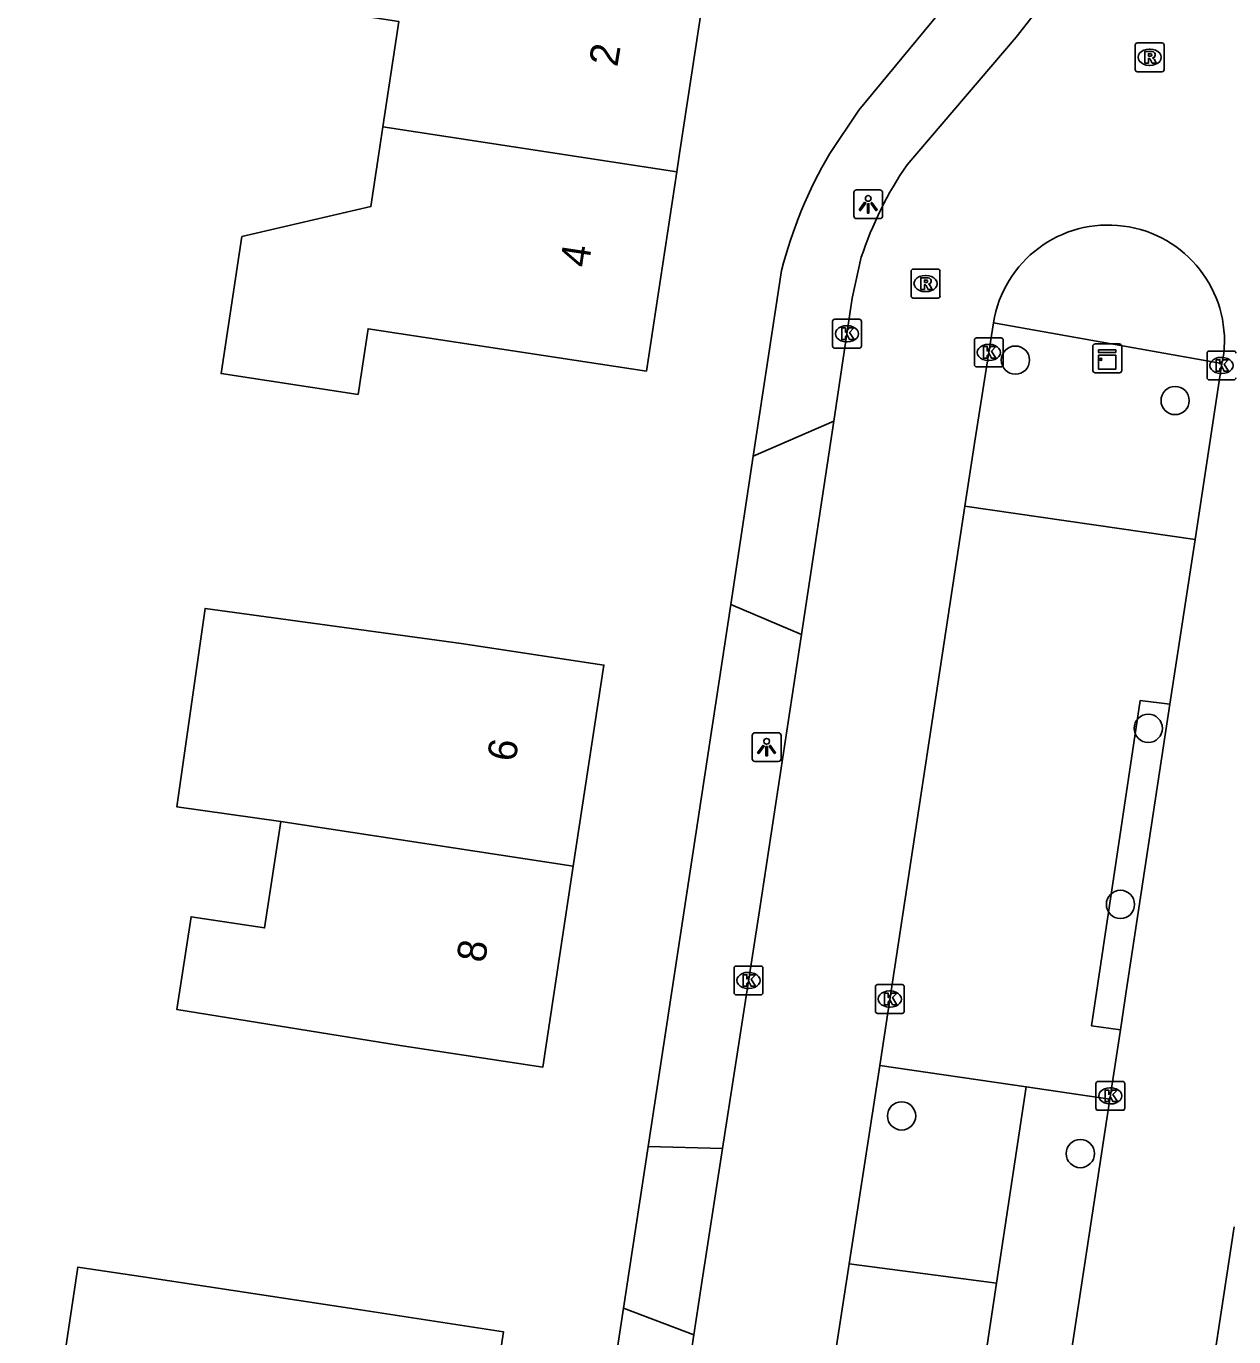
# Model space of a CAD drawing. Extents: x 161486 to 162249, y 379484 to 380829.
# Drawn here: x 161878.74 to 161920.56, y 380459.01 to 380504.41 of the extents above; entities that cross this region are included whole.
import ezdxf

# ---------------------------------------------------------------- set-up
doc = ezdxf.new("R2010")
doc.units = 0
for name, color, linetype in [('IMGEO_Boom', 7, 'Continuous'), ('IMGEO_Groenvoorziening', 7, 'Continuous'), ('IMGEO_Kast', 7, 'Continuous'), ('IMGEO_Kolk', 7, 'Continuous'), ('IMGEO_Lichtpunt', 7, 'Continuous'), ('IMGEO_Pand', 7, 'Continuous'), ('IMGEO_Pand_nummerreeks', 7, 'Continuous'), ('IMGEO_Rijbaan_lokaal_open', 7, 'Continuous'), ('IMGEO_Rioolput', 7, 'Continuous'), ('IMGEO_Voetpad_open', 7, 'Continuous')]:
    doc.layers.add(name, color=color, linetype=linetype)

msp = doc.modelspace()

# ---------------------------------------------------------------- linework, layer by layer
at = {"layer": 'IMGEO_Boom'}
for centre in [(161912.998, 380492.844), (161918.53, 380491.445), (161917.601, 380480.089), (161916.638, 380473.989), (161909.055, 380466.663), (161915.247, 380465.358)]:
    msp.add_circle(centre, 0.489, dxfattribs=at)
at = {"layer": 'IMGEO_Groenvoorziening'}
for points in [[(161919.219, 380486.625), (161911.251, 380487.786)], [(161916.636, 380469.648), (161915.634, 380469.779), (161917.32, 380481.052), (161918.352, 380480.926)], [(161908.297, 380468.414), (161913.37, 380467.67)], [(161912.348, 380460.87), (161913.37, 380467.67)], [(161913.37, 380467.67), (161916.269, 380467.244)], [(161912.348, 380460.87), (161907.235, 380461.539)], [(161908.746, 380436.913), (161912.348, 380460.87)]]:
    msp.add_lwpolyline(points, dxfattribs=at)
at = {"layer": 'IMGEO_Kast'}
for p, q in [((161915.68, 380492.481), (161915.68, 380493.322)), ((161915.68, 380493.322), (161915.68, 380492.481)), ((161915.755, 380493.406), (161916.596, 380493.406)), ((161916.596, 380493.406), (161915.755, 380493.406)), ((161916.68, 380493.331), (161916.68, 380492.49)), ((161916.68, 380492.49), (161916.68, 380493.331)), ((161916.605, 380492.406), (161915.764, 380492.406)), ((161915.764, 380492.406), (161916.605, 380492.406))]:
    msp.add_line(p, q, dxfattribs=at)
for points in [[(161915.875, 380493.196), (161916.475, 380493.196), (161916.475, 380493.111), (161915.875, 380493.111), (161915.875, 380493.196)], [(161915.875, 380493.021), (161916.475, 380493.021), (161916.475, 380492.532), (161915.875, 380492.532), (161915.875, 380493.021)]]:
    msp.add_lwpolyline(points, dxfattribs=at)
msp.add_circle((161915.959, 380492.87), 0.0377, dxfattribs=at)
for centre, start, end in [((161915.758, 380493.328), 92.4484, 184.2845), ((161915.758, 380493.328), 92.4484, 184.2845), ((161916.602, 380493.328), 2.4484, 94.2845), ((161916.602, 380493.328), 2.4484, 94.2845), ((161915.758, 380492.484), 182.4484, 274.2845), ((161915.758, 380492.484), 182.4484, 274.2845), ((161916.602, 380492.484), 272.4484, 4.2845), ((161916.602, 380492.484), 272.4484, 4.2845)]:
    msp.add_arc(centre, 0.0779, start, end, dxfattribs=at)
at = {"layer": 'IMGEO_Kolk'}
for p, q in [((161906.739, 380494.258), (161907.591, 380494.258)), ((161906.664, 380493.332), (161906.664, 380494.184)), ((161907.152, 380494.038), (161907.177, 380494.038)), ((161907.665, 380494.184), (161907.665, 380493.332)), ((161907.175, 380493.478), (161907.15, 380493.478)), ((161911.577, 380492.685), (161911.577, 380493.537)), ((161911.652, 380493.611), (161912.504, 380493.611)), ((161912.065, 380493.391), (161912.09, 380493.391)), ((161912.578, 380493.537), (161912.578, 380492.685)), ((161907.591, 380493.258), (161906.739, 380493.258)), ((161919.635, 380492.234), (161919.635, 380493.086)), ((161919.71, 380493.16), (161920.562, 380493.16)), ((161920.123, 380492.94), (161920.148, 380492.94)), ((161912.504, 380492.611), (161911.652, 380492.611)), ((161912.088, 380492.831), (161912.063, 380492.831)), ((161920.562, 380492.16), (161919.71, 380492.16)), ((161920.146, 380492.38), (161920.121, 380492.38)), ((161903.252, 380470.929), (161903.252, 380471.781)), ((161903.327, 380471.855), (161904.179, 380471.855)), ((161903.74, 380471.635), (161903.765, 380471.635)), ((161904.253, 380471.781), (161904.253, 380470.929)), ((161903.763, 380471.075), (161903.738, 380471.075)), ((161908.148, 380470.286), (161908.148, 380471.138)), ((161908.223, 380471.212), (161909.075, 380471.212)), ((161909.149, 380471.138), (161909.149, 380470.286)), ((161904.179, 380470.855), (161903.327, 380470.855)), ((161908.636, 380470.992), (161908.661, 380470.992)), ((161909.075, 380470.212), (161908.223, 380470.212)), ((161908.659, 380470.432), (161908.634, 380470.432)), ((161915.785, 380466.931), (161915.785, 380467.783)), ((161915.86, 380467.857), (161916.712, 380467.857)), ((161916.273, 380467.637), (161916.298, 380467.637)), ((161916.786, 380467.783), (161916.786, 380466.931)), ((161916.296, 380467.077), (161916.271, 380467.077)), ((161916.712, 380466.857), (161915.86, 380466.857))]:
    msp.add_line(p, q, dxfattribs=at)
for points in [[(161906.739, 380494.258), (161907.591, 380494.258)], [(161906.664, 380493.332), (161906.664, 380494.184)], [(161906.985, 380493.958), (161907.108, 380493.958), (161907.108, 380493.807), (161907.238, 380493.958), (161907.402, 380493.958), (161907.256, 380493.807), (161907.409, 380493.558), (161907.257, 380493.558), (161907.172, 380493.722), (161907.108, 380493.655), (161907.108, 380493.558), (161906.985, 380493.558), (161906.985, 380493.958)], [(161907.665, 380494.184), (161907.665, 380493.332)], [(161911.577, 380492.685), (161911.577, 380493.537)], [(161911.652, 380493.611), (161912.504, 380493.611)], [(161911.898, 380493.311), (161912.021, 380493.311), (161912.021, 380493.16), (161912.151, 380493.311), (161912.315, 380493.311), (161912.169, 380493.16), (161912.322, 380492.911), (161912.17, 380492.911), (161912.085, 380493.075), (161912.021, 380493.008), (161912.021, 380492.911), (161911.898, 380492.911), (161911.898, 380493.311)], [(161912.578, 380493.537), (161912.578, 380492.685)], [(161907.591, 380493.258), (161906.739, 380493.258)], [(161919.635, 380492.234), (161919.635, 380493.086)], [(161919.71, 380493.16), (161920.562, 380493.16)], [(161919.956, 380492.86), (161920.079, 380492.86), (161920.079, 380492.709), (161920.209, 380492.86), (161920.373, 380492.86), (161920.227, 380492.709), (161920.38, 380492.46), (161920.228, 380492.46), (161920.143, 380492.624), (161920.079, 380492.557), (161920.079, 380492.46), (161919.956, 380492.46), (161919.956, 380492.86)], [(161912.504, 380492.611), (161911.652, 380492.611)], [(161920.562, 380492.16), (161919.71, 380492.16)], [(161903.252, 380470.929), (161903.252, 380471.781)], [(161903.327, 380471.855), (161904.179, 380471.855)], [(161903.573, 380471.555), (161903.696, 380471.555), (161903.696, 380471.404), (161903.826, 380471.555), (161903.99, 380471.555), (161903.844, 380471.404), (161903.997, 380471.155), (161903.845, 380471.155), (161903.76, 380471.319), (161903.696, 380471.252), (161903.696, 380471.155), (161903.573, 380471.155), (161903.573, 380471.555)], [(161904.253, 380471.781), (161904.253, 380470.929)], [(161908.148, 380470.286), (161908.148, 380471.138)], [(161908.223, 380471.212), (161909.075, 380471.212)], [(161909.149, 380471.138), (161909.149, 380470.286)], [(161904.179, 380470.855), (161903.327, 380470.855)], [(161908.469, 380470.912), (161908.592, 380470.912), (161908.592, 380470.761), (161908.722, 380470.912), (161908.886, 380470.912), (161908.74, 380470.761), (161908.893, 380470.512), (161908.741, 380470.512), (161908.656, 380470.676), (161908.592, 380470.609), (161908.592, 380470.512), (161908.469, 380470.512), (161908.469, 380470.912)], [(161909.075, 380470.212), (161908.223, 380470.212)], [(161915.785, 380466.931), (161915.785, 380467.783)], [(161915.86, 380467.857), (161916.712, 380467.857)], [(161916.106, 380467.557), (161916.229, 380467.557), (161916.229, 380467.406), (161916.359, 380467.557), (161916.523, 380467.557), (161916.377, 380467.406), (161916.53, 380467.157), (161916.378, 380467.157), (161916.293, 380467.321), (161916.229, 380467.254), (161916.229, 380467.157), (161916.106, 380467.157), (161916.106, 380467.557)], [(161916.786, 380467.783), (161916.786, 380466.931)], [(161916.712, 380466.857), (161915.86, 380466.857)]]:
    msp.add_lwpolyline(points, dxfattribs=at)
for centre, start, end in [((161906.741, 380494.182), 91.552, 178.448), ((161906.741, 380494.182), 91.552, 178.448), ((161907.589, 380494.182), 1.552, 88.448), ((161907.589, 380494.182), 1.552, 88.448), ((161906.741, 380493.334), 181.552, 268.448), ((161906.741, 380493.334), 181.552, 268.448), ((161907.589, 380493.334), 271.552, 358.448), ((161907.589, 380493.334), 271.552, 358.448), ((161911.654, 380493.535), 91.552, 178.448), ((161911.654, 380493.535), 91.552, 178.448), ((161912.502, 380493.535), 1.552, 88.448), ((161912.502, 380493.535), 1.552, 88.448), ((161919.712, 380493.084), 91.552, 178.448), ((161919.712, 380493.084), 91.552, 178.448), ((161920.56, 380493.084), 1.552, 88.448), ((161920.56, 380493.084), 1.552, 88.448), ((161911.654, 380492.687), 181.552, 268.448), ((161911.654, 380492.687), 181.552, 268.448), ((161912.502, 380492.687), 271.552, 358.448), ((161912.502, 380492.687), 271.552, 358.448), ((161919.712, 380492.236), 181.552, 268.448), ((161919.712, 380492.236), 181.552, 268.448), ((161920.56, 380492.236), 271.552, 358.448), ((161920.56, 380492.236), 271.552, 358.448), ((161903.329, 380471.779), 91.552, 178.448), ((161903.329, 380471.779), 91.552, 178.448), ((161904.177, 380471.779), 1.552, 88.448), ((161904.177, 380471.779), 1.552, 88.448), ((161908.225, 380471.136), 91.552, 178.448), ((161908.225, 380471.136), 91.552, 178.448), ((161909.073, 380471.136), 1.552, 88.448), ((161909.073, 380471.136), 1.552, 88.448), ((161903.329, 380470.931), 181.552, 268.448), ((161903.329, 380470.931), 181.552, 268.448), ((161904.177, 380470.931), 271.552, 358.448), ((161904.177, 380470.931), 271.552, 358.448), ((161908.225, 380470.288), 181.552, 268.448), ((161908.225, 380470.288), 181.552, 268.448), ((161909.073, 380470.288), 271.552, 358.448), ((161909.073, 380470.288), 271.552, 358.448), ((161915.862, 380467.781), 91.552, 178.448), ((161915.862, 380467.781), 91.552, 178.448), ((161916.71, 380467.781), 1.552, 88.448), ((161916.71, 380467.781), 1.552, 88.448), ((161915.862, 380466.933), 181.552, 268.448), ((161915.862, 380466.933), 181.552, 268.448), ((161916.71, 380466.933), 271.552, 358.448), ((161916.71, 380466.933), 271.552, 358.448)]:
    msp.add_arc(centre, 0.0765, start, end, dxfattribs=at)
for centre, major_axis, ratio, start_param, end_param in [((161907.151, 380493.758), (-0.387, 0.002), 0.722429, 4.712389, 7.853982), ((161907.176, 380493.758), (-0.39, 0.002), 0.717154, 1.570796, 4.712389), ((161912.064, 380493.111), (-0.387, 0.002), 0.722429, 4.712389, 7.853982), ((161912.089, 380493.111), (-0.39, 0.002), 0.717154, 1.570796, 4.712389), ((161920.122, 380492.66), (-0.387, 0.002), 0.722429, 4.712389, 7.853982), ((161920.147, 380492.66), (-0.39, 0.002), 0.717154, 1.570796, 4.712389), ((161903.739, 380471.355), (-0.387, 0.002), 0.722429, 4.712389, 7.853982), ((161903.764, 380471.355), (-0.39, 0.002), 0.717154, 1.570796, 4.712389), ((161908.635, 380470.712), (-0.387, 0.002), 0.722429, 4.712389, 7.853982), ((161908.66, 380470.712), (-0.39, 0.002), 0.717154, 1.570796, 4.712389), ((161916.272, 380467.357), (-0.387, 0.002), 0.722429, 4.712389, 7.853982), ((161916.297, 380467.357), (-0.39, 0.002), 0.717154, 1.570796, 4.712389)]:
    msp.add_ellipse(centre, major_axis=major_axis, ratio=ratio, start_param=start_param, end_param=end_param, dxfattribs=at)
at = {"layer": 'IMGEO_Lichtpunt'}
for p, q in [((161907.401, 380498.647), (161907.401, 380497.84)), ((161907.401, 380498.647), (161907.401, 380497.84)), ((161908.303, 380498.742), (161907.495, 380498.742)), ((161908.303, 380498.742), (161907.495, 380498.742)), ((161908.397, 380497.84), (161908.397, 380498.647)), ((161908.397, 380497.84), (161908.397, 380498.647)), ((161907.495, 380497.746), (161908.303, 380497.746)), ((161907.495, 380497.746), (161908.303, 380497.746)), ((161903.883, 380479.841), (161903.883, 380479.034)), ((161903.883, 380479.841), (161903.883, 380479.034)), ((161904.785, 380479.936), (161903.977, 380479.936)), ((161904.785, 380479.936), (161903.977, 380479.936)), ((161904.879, 380479.034), (161904.879, 380479.841)), ((161904.879, 380479.034), (161904.879, 380479.841)), ((161903.977, 380478.94), (161904.785, 380478.94)), ((161903.977, 380478.94), (161904.785, 380478.94))]:
    msp.add_line(p, q, dxfattribs=at)
for points in [[(161907.775, 380498.311), (161907.814, 380498.283), (161907.626, 380498.021), (161907.588, 380498.048), (161907.775, 380498.311)], [(161907.987, 380498.283), (161908.025, 380498.31), (161908.212, 380498.048), (161908.173, 380498.02), (161907.987, 380498.283)], [(161907.877, 380498.263), (161907.924, 380498.263), (161907.924, 380497.941), (161907.877, 380497.941), (161907.877, 380498.263)], [(161904.257, 380479.505), (161904.296, 380479.477), (161904.108, 380479.215), (161904.07, 380479.242), (161904.257, 380479.505)], [(161904.359, 380479.457), (161904.406, 380479.457), (161904.406, 380479.135), (161904.359, 380479.135), (161904.359, 380479.457)], [(161904.469, 380479.477), (161904.507, 380479.504), (161904.694, 380479.242), (161904.655, 380479.214), (161904.469, 380479.477)]]:
    msp.add_lwpolyline(points, dxfattribs=at)
for centre in [(161907.9, 380498.445), (161904.382, 380479.639)]:
    msp.add_circle(centre, 0.0994, dxfattribs=at)
for centre, start, end in [((161907.495, 380498.647), 90, 180), ((161907.495, 380498.647), 90, 180), ((161908.303, 380498.647), 0, 90), ((161908.303, 380498.647), 0, 90), ((161907.495, 380497.84), 180, 270), ((161907.495, 380497.84), 180, 270), ((161908.303, 380497.84), 270, 0), ((161908.303, 380497.84), 270, 360), ((161903.977, 380479.841), 90, 180), ((161903.977, 380479.841), 90, 180), ((161904.785, 380479.841), 0, 90), ((161904.785, 380479.841), 0, 90), ((161903.977, 380479.034), 180, 270), ((161903.977, 380479.034), 180, 270), ((161904.785, 380479.034), 270, 0), ((161904.785, 380479.034), 270, 360)]:
    msp.add_arc(centre, 0.0946, start, end, dxfattribs=at)
at = {"layer": 'IMGEO_Pand'}
for points in [[(161891.087, 380500.923), (161891.637, 380504.58), (161889.15, 380504.959), (161888.417, 380505.064), (161888.668, 380506.71), (161886.742, 380506.985), (161887.229, 380510.177), (161893.554, 380509.272), (161893.313, 380507.589), (161897.375, 380507.031), (161902.318, 380506.279), (161901.363, 380500), (161901.267, 380499.372)], [(161901.267, 380499.372), (161900.216, 380492.465), (161890.577, 380493.931), (161890.231, 380491.658), (161885.486, 380492.38), (161886.208, 380497.125), (161890.672, 380498.165), (161890.948, 380500), (161891.087, 380500.923)], [(161901.267, 380499.372), (161891.087, 380500.923)], [(161887.553, 380476.857), (161883.953, 380477.369), (161884.931, 380484.242), (161885.953, 380484.097), (161893.801, 380483.03), (161898.744, 380482.278), (161897.685, 380475.315)], [(161897.685, 380475.315), (161896.626, 380468.349), (161891.683, 380469.101), (161883.954, 380470.346), (161884.443, 380473.564), (161886.993, 380473.176), (161887.553, 380476.857)], [(161887.553, 380476.857), (161897.685, 380475.315)], [(161879.181, 380454.13), (161882.864, 380453.571), (161883.438, 380457.35), (161882.251, 380457.531), (161879.988, 380457.875), (161880.528, 380461.428), (161882.791, 380461.084), (161890.319, 380459.94), (161895.262, 380459.188), (161894.143, 380451.825), (161889.2, 380452.576), (161884.046, 380453.36), (161883.605, 380450.458), (161878.735, 380451.198), (161879.181, 380454.13)]]:
    msp.add_lwpolyline(points, dxfattribs=at)
at = {"layer": 'IMGEO_Rijbaan_lokaal_open'}
for points in [[(161913.613, 380504.779), (161913.02, 380504.036), (161909.582, 380500), (161909.249, 380499.609)], [(161907.66, 380496.406), (161907.349, 380494.99), (161906.714, 380490.728)], [(161911.251, 380487.786), (161911.595, 380490.039), (161912.237, 380494.134)], [(161920.218, 380493.077), (161920.146, 380492.723)], [(161920.146, 380492.723), (161919.219, 380486.625)], [(161906.714, 380490.728), (161905.587, 380483.336)], [(161908.297, 380468.414), (161911.251, 380487.786)], [(161919.219, 380486.625), (161918.352, 380480.926)], [(161905.587, 380483.336), (161904.129, 380473.778), (161902.851, 380465.53)], [(161918.352, 380480.926), (161916.839, 380470.975), (161916.636, 380469.648)], [(161916.636, 380469.648), (161916.269, 380467.244)], [(161907.235, 380461.539), (161908.297, 380468.414)], [(161916.269, 380467.244), (161913.458, 380448.83), (161909.61, 380423.559), (161908.667, 380417.626)], [(161902.851, 380465.53), (161902.098, 380460.673), (161901.858, 380459.079)], [(161919.434, 380455.31), (161920.58, 380462.821)], [(161903.567, 380437.693), (161904.441, 380443.444), (161907.235, 380461.539)], [(161901.858, 380459.079), (161900.447, 380449.706), (161899.998, 380446.856)]]:
    msp.add_lwpolyline(points, dxfattribs=at)
for centre, radius, start, end in [((161919.492, 380492.532), 12.45, 145.3584, 161.8698), ((161916.213, 380493.498), 4.027, 353.9979, 170.9134)]:
    msp.add_arc(centre, radius, start, end, dxfattribs=at)
at = {"layer": 'IMGEO_Rioolput'}
for p, q in [((161917.147, 380502.91), (161917.147, 380503.762)), ((161917.222, 380503.836), (161918.074, 380503.836)), ((161918.148, 380503.762), (161918.148, 380502.91)), ((161917.635, 380503.616), (161917.66, 380503.616)), ((161918.074, 380502.836), (161917.222, 380502.836)), ((161917.658, 380503.056), (161917.633, 380503.056)), ((161909.385, 380495.07), (161909.385, 380495.922)), ((161909.46, 380495.996), (161910.312, 380495.996)), ((161909.873, 380495.776), (161909.898, 380495.776)), ((161910.386, 380495.922), (161910.386, 380495.07)), ((161909.896, 380495.216), (161909.871, 380495.216)), ((161910.312, 380494.996), (161909.46, 380494.996))]:
    msp.add_line(p, q, dxfattribs=at)
for points in [[(161917.147, 380502.91), (161917.147, 380503.762)], [(161917.222, 380503.836), (161918.074, 380503.836)], [(161918.148, 380503.762), (161918.148, 380502.91)], [(161917.736, 380503.534), (161917.484, 380503.536), (161917.484, 380503.136)], [(161917.484, 380503.136), (161917.608, 380503.136), (161917.608, 380503.298), (161917.619, 380503.298)], [(161917.662, 380503.455), (161917.608, 380503.455), (161917.608, 380503.374)], [(161917.608, 380503.374), (161917.66, 380503.374)], [(161918.074, 380502.836), (161917.222, 380502.836)], [(161917.666, 380503.269), (161917.737, 380503.136), (161917.877, 380503.136), (161917.812, 380503.262)], [(161909.385, 380495.07), (161909.385, 380495.922)], [(161909.46, 380495.996), (161910.312, 380495.996)], [(161909.974, 380495.694), (161909.722, 380495.696), (161909.722, 380495.296)], [(161909.9, 380495.615), (161909.846, 380495.615), (161909.846, 380495.534)], [(161910.386, 380495.922), (161910.386, 380495.07)], [(161909.722, 380495.296), (161909.846, 380495.296), (161909.846, 380495.458), (161909.857, 380495.458)], [(161909.846, 380495.534), (161909.898, 380495.534)], [(161909.904, 380495.429), (161909.975, 380495.296), (161910.115, 380495.296), (161910.05, 380495.422)], [(161910.312, 380494.996), (161909.46, 380494.996)]]:
    msp.add_lwpolyline(points, dxfattribs=at)
for centre, radius, start, end in [((161917.224, 380503.76), 0.0765, 91.552, 178.448), ((161917.224, 380503.76), 0.0765, 91.552, 178.448), ((161918.072, 380503.76), 0.0765, 1.552, 88.448), ((161918.072, 380503.76), 0.0765, 1.552, 88.448), ((161917.618, 380503.245), 0.0533, 26.0293, 88.6989), ((161917.644, 380503.563), 0.19, 274.7715, 282.9687), ((161917.668, 380503.359), 0.0964, 77.0061, 93.1865), ((161917.682, 380503.416), 0.0378, 276.6634, 79.6772), ((161917.735, 380503.424), 0.109, 350.3612, 89.416), ((161917.733, 380503.424), 0.112, 277.5842, 350.9817), ((161917.717, 380503.209), 0.108, 29.5134, 73.7905), ((161917.224, 380502.912), 0.0765, 181.552, 268.448), ((161917.224, 380502.912), 0.0765, 181.552, 268.448), ((161918.072, 380502.912), 0.0765, 271.552, 358.448), ((161918.072, 380502.912), 0.0765, 271.552, 358.448), ((161909.462, 380495.92), 0.0765, 91.552, 178.448), ((161909.462, 380495.92), 0.0765, 91.552, 178.448), ((161909.906, 380495.519), 0.0964, 77.0061, 93.1865), ((161909.92, 380495.576), 0.0378, 276.6634, 79.6772), ((161909.973, 380495.584), 0.109, 350.3612, 89.416), ((161910.31, 380495.92), 0.0765, 1.552, 88.448), ((161910.31, 380495.92), 0.0765, 1.552, 88.448), ((161909.856, 380495.405), 0.0533, 26.0293, 88.6989), ((161909.882, 380495.723), 0.19, 274.7715, 282.9687), ((161909.971, 380495.584), 0.112, 277.5842, 350.9817), ((161909.955, 380495.369), 0.108, 29.5134, 73.7905), ((161909.462, 380495.072), 0.0765, 181.552, 268.448), ((161909.462, 380495.072), 0.0765, 181.552, 268.448), ((161910.31, 380495.072), 0.0765, 271.552, 358.448), ((161910.31, 380495.072), 0.0765, 271.552, 358.448)]:
    msp.add_arc(centre, radius, start, end, dxfattribs=at)
for centre, major_axis, ratio, start_param, end_param in [((161917.634, 380503.336), (-0.387, 0.002), 0.722429, 4.712389, 7.853982), ((161917.659, 380503.336), (-0.39, 0.002), 0.717154, 1.570796, 4.712389), ((161909.872, 380495.496), (-0.387, 0.002), 0.722429, 4.712389, 7.853982), ((161909.897, 380495.496), (-0.39, 0.002), 0.717154, 1.570796, 4.712389)]:
    msp.add_ellipse(centre, major_axis=major_axis, ratio=ratio, start_param=start_param, end_param=end_param, dxfattribs=at)
at = {"layer": 'IMGEO_Voetpad_open'}
for points in [[(161906.568, 380500), (161907.579, 380501.499), (161911.601, 380506.388)], [(161903.92, 380489.515), (161904.9, 380495.947)], [(161912.237, 380494.134), (161920.146, 380492.723)], [(161903.92, 380489.515), (161906.714, 380490.728)], [(161903.137, 380484.376), (161903.92, 380489.515)], [(161900.279, 380465.607), (161903.137, 380484.376)], [(161905.587, 380483.336), (161903.137, 380484.376)], [(161899.426, 380460.006), (161900.279, 380465.607)], [(161900.279, 380465.607), (161902.851, 380465.53)], [(161897.419, 380446.831), (161899.426, 380460.006)], [(161901.858, 380459.079), (161899.426, 380460.006)]]:
    msp.add_lwpolyline(points, dxfattribs=at)
msp.add_arc((161919.629, 380492.255), 15.184, 149.3327, 165.9284, dxfattribs=at)

# ---------------------------------------------------------------- texts
at = {"layer": 'IMGEO_Pand_nummerreeks'}
for s, rotation, p in [('2', 80.4521, (161899.208, 380502.978)), ('4', 81.348, (161898.209, 380496.026)), ('6', 81.354, (161895.681, 380478.903)), ('8', 81.354, (161894.623, 380471.942))]:
    msp.add_text(s, height=1, rotation=rotation, dxfattribs=at).set_placement(p)

doc.saveas('drawing.dxf')
